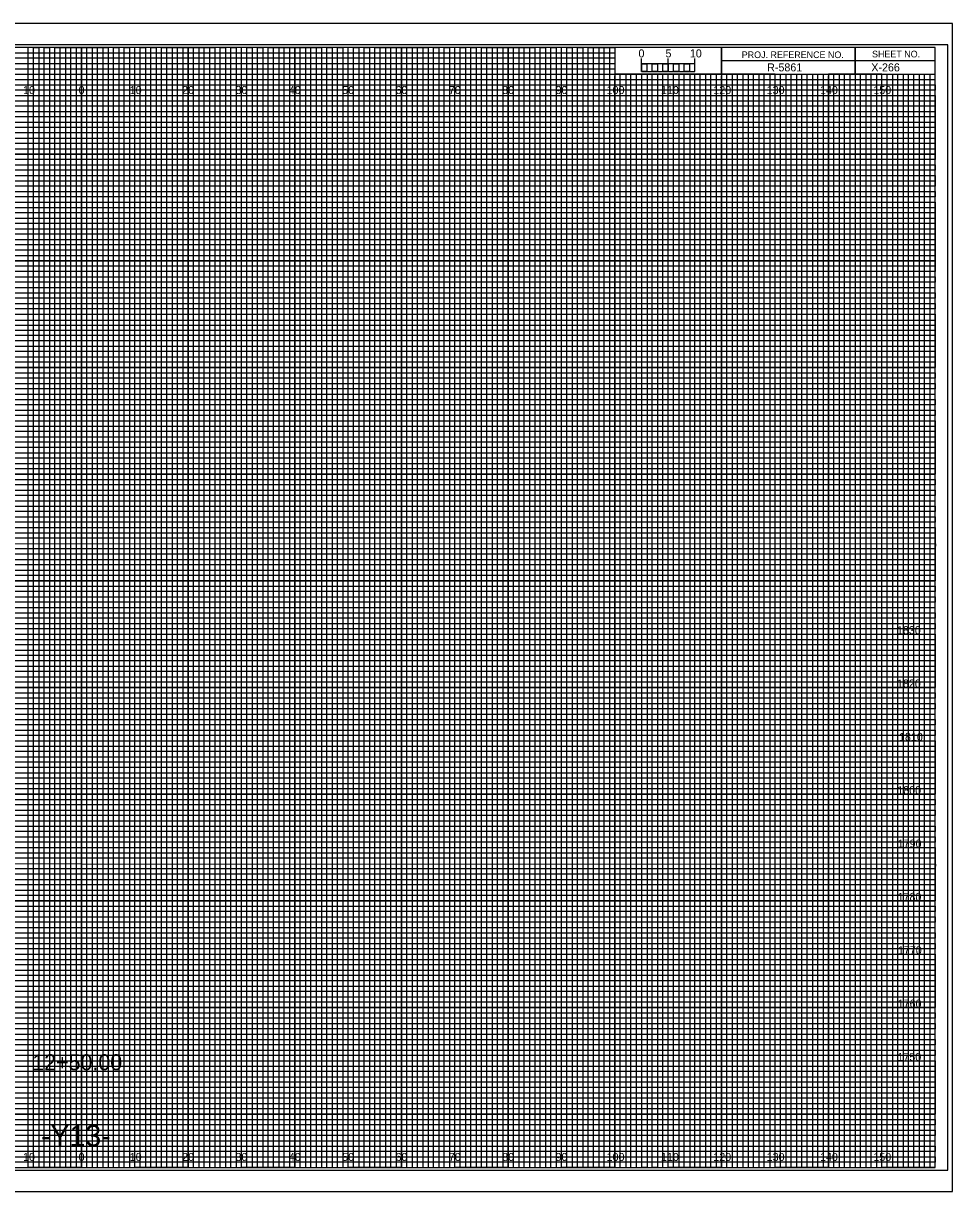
# Model space of a CAD drawing. Extents: x -13 to 323, y -5 to 654.
# Drawn here: x 149.1 to 323.3, y 435.5 to 654.5 of the extents above; entities that cross this region are included whole.
import ezdxf

# ---------------------------------------------------------------- set-up
doc = ezdxf.new("R2010")
doc.units = 0
for name, color, linetype in [('Prop Horizontal Alignment', 7, 'Continuous'), ('Prop XS Alignment Label', 7, 'Continuous'), ('Prop XS Bar Scale Labels', 7, 'Continuous'), ('Prop XS DDE', 7, 'Continuous'), ('Prop XS Earthwork Shape', 7, 'Continuous'), ('Prop XS Project Number', 7, 'Continuous'), ('Prop XS Sheet Number', 7, 'Continuous'), ('Raster_Level_0', 7, 'Continuous'), ('Scratch_Level_3', 7, 'Continuous'), ('Sheet Cross Section CELL', 7, 'Continuous'), ('Sheet Cross Section Grid Minor 1 CELL', 7, 'Continuous'), ('Sheet Cross Section Grid Minor 2 CELL', 7, 'Continuous'), ('Sheet Cross Section Scale CELL', 7, 'Continuous'), ('Sheet Cutting Line CELL', 7, 'Continuous'), ('Sheet DOT Grid CELL', 7, 'Continuous'), ('Sheet Plot Border Inside CELL', 7, 'Continuous'), ('Sheet Plot Border Outside CELL', 7, 'Continuous')]:
    doc.layers.add(name, color=color, linetype=linetype)

msp = doc.modelspace()

# ---------------------------------------------------------------- linework, layer by layer
at = {"layer": 'Prop XS DDE'}
for points in [[(145, 440), (155, 440), (155, 650), (165, 650), (165, 440), (175, 440), (175, 650), (185, 650), (185, 440), (195, 440), (195, 650), (205, 650), (205, 440), (215, 440), (215, 650), (225, 650), (225, 440), (235, 440), (235, 650), (245, 650), (245, 440), (255, 440), (255, 650), (259.93, 650), (260, 650), (260, 645), (264.99, 645), (264.99, 440), (275, 440), (275, 645), (285, 645), (285, 440), (295, 440), (295, 645), (305, 645), (305, 440), (315, 440), (315, 645)], [(0, 645), (275, 645)], [(0, 625), (320, 625), (320, 635), (0, 635)], [(0, 605), (320, 605), (320, 615), (0, 615)], [(0, 585), (320, 585), (320, 595), (0, 595)], [(0, 565), (320, 565), (320, 575), (0, 575)], [(0, 545), (320, 545), (320, 555), (0, 555)], [(0, 525), (320, 525), (320, 535), (0, 535)], [(0, 505), (320, 505), (320, 515), (0, 515)], [(0, 485), (320, 485), (320, 495), (0, 495)], [(0, 465), (320, 465), (320, 475), (0, 475)], [(0, 445), (320, 445), (320, 455), (0, 455)]]:
    msp.add_lwpolyline(points, dxfattribs=at)
at = {"layer": 'Prop XS Earthwork Shape'}
for p, q in [((150, 650), (140, 650)), ((150, 440), (150, 650)), ((170, 650), (160, 650)), ((160, 650), (160, 440)), ((170, 440), (170, 650)), ((190, 650), (180, 650)), ((180, 650), (180, 440)), ((190, 440), (190, 650)), ((210, 650), (200, 650)), ((200, 650), (200, 440)), ((210, 440), (210, 650)), ((230, 650), (220, 650)), ((220, 650), (220, 440)), ((230, 440), (230, 650)), ((250, 650), (240, 650)), ((240, 650), (240, 440)), ((250, 440), (250, 650)), ((260, 650), (260, 440)), ((270, 440), (270, 645)), ((290, 645), (280, 645)), ((280, 645), (280, 440)), ((290, 440), (290, 645)), ((310, 645), (300, 645)), ((300, 645), (300, 440)), ((310, 440), (310, 645)), ((160, 440), (150, 440)), ((180, 440), (170, 440)), ((200, 440), (190, 440)), ((220, 440), (210, 440)), ((240, 440), (230, 440)), ((260, 440), (250, 440)), ((280, 440), (270, 440)), ((300, 440), (290, 440)), ((320, 440), (310, 440)), ((320, 440), (320, 440))]:
    msp.add_line(p, q, dxfattribs=at)
for points in [[(0, 640), (320, 640), (320, 630), (0, 630)], [(0, 620), (320, 620), (320, 610), (0, 610)], [(0, 600), (320, 600), (320, 590), (0, 590)], [(0, 580), (320, 580), (320, 570), (0, 570)], [(0, 560), (320, 560), (320, 550), (0, 550)], [(0, 540), (320, 540), (320, 530), (0, 530)], [(0, 520), (320, 520), (320, 510), (0, 510)], [(0, 500), (320, 500), (320, 490), (0, 490)], [(0, 480), (320, 480), (320, 470), (0, 470)], [(0, 460), (320, 460), (320, 450), (0, 450)]]:
    msp.add_lwpolyline(points, dxfattribs=at)
at = {"layer": 'Sheet Cross Section CELL'}
for p, q in [((305, 650), (305, 645)), ((305, 645), (305, 650)), ((280, 647.5), (280, 645)), ((320, 647.49), (280, 647.49)), ((280, 645), (320, 645))]:
    msp.add_line(p, q, dxfattribs=at)
for points in [[(320, 650), (0, 650), (0, 440), (320, 440)], [(280, 650), (260, 650), (260, 645.03), (280, 645.03)], [(320, 650), (280, 650), (280, 645), (320, 645)]]:
    msp.add_lwpolyline(points, close=True, dxfattribs=at)
at = {"layer": 'Sheet Cross Section Grid Minor 1 CELL'}
for p, q in [((0, 649), (260, 649)), ((260, 649), (260, 647.98)), ((260, 647.98), (0, 647.98)), ((0, 647), (260, 647)), ((260, 647), (260, 645.89)), ((260, 645.89), (0, 645.89)), ((0, 644), (320, 644))]:
    msp.add_line(p, q, dxfattribs=at)
for points in [[(0, 643), (270, 643), (320, 643), (320, 642), (0, 642)], [(0, 641), (320, 641), (320, 639), (0, 639)], [(0, 638), (320, 638), (320, 637), (0, 636.98)], [(0, 636), (320, 636), (320, 634), (0, 634)], [(0, 633), (320, 633), (320, 632), (0, 632)], [(0, 631), (320, 631), (320, 629), (0, 629)], [(0, 628), (320, 628), (320, 627), (0, 627)], [(0, 626), (320, 626), (320, 624), (0, 624)], [(0, 623), (320, 623), (320, 622), (0, 622)], [(0, 621), (320, 621), (320, 619), (0, 619)], [(0, 618), (320, 618), (320, 617), (0, 617)], [(0, 616), (320, 616), (320, 613.95), (320, 613), (320, 612), (0, 612)], [(0, 614), (320, 614), (320, 613), (0, 613)], [(0, 611), (320, 611), (320, 609), (0, 609.03)], [(0, 609.03), (320, 609), (320, 608), (0, 608)], [(0, 607), (320, 607), (320, 606), (0, 606)], [(0, 604), (320, 604), (320, 603), (0, 603)], [(0, 602), (320, 602), (320, 601), (0, 601)], [(-0.07, 598.89), (320, 598.89), (320, 597.88), (-0.07, 597.88)], [(0, 597), (320, 597), (320, 596), (0, 596)], [(0, 594), (320, 594), (320, 593), (0, 593)], [(0, 592), (320, 592), (320, 591), (0, 591)], [(0, 589), (320, 589), (320, 588), (0, 588)], [(0, 587), (320, 587), (320, 586), (0, 586)], [(0, 584), (320, 584), (320, 583), (0, 583)], [(0, 582), (320, 582), (320, 581), (0, 581)], [(0, 579), (320, 579), (319.99, 577.98), (0, 578)], [(0, 577), (320, 577), (320, 576), (0, 576)], [(0, 574), (320, 574), (320, 573), (0, 573)], [(0, 572), (320, 572), (320, 571), (0, 571)], [(0, 569), (320, 569), (320, 568), (0, 568)], [(0, 567), (320, 567), (320, 566), (0, 566)], [(0, 564), (320, 564), (320, 563), (0, 563)], [(0, 562), (320, 562), (320, 561), (0, 561)], [(0, 559), (320, 559), (320, 558), (0, 558)], [(0, 556.99), (320.07, 556.91), (320, 556), (0, 556)], [(0, 554), (320, 554), (320, 553), (0, 553)], [(0, 552), (320, 552), (320, 551), (0, 551)], [(0, 549), (320, 549), (320, 548), (0, 548)], [(0, 547), (320, 547), (320, 546), (0, 546)], [(0, 544), (320, 544), (320, 543), (0, 543)], [(0, 542), (320, 542), (320, 541), (0, 541)], [(0, 539), (320, 539), (320, 538), (0, 538)], [(0, 537), (320, 537), (320, 536), (0, 536)], [(0, 534), (320, 534), (320, 533), (0, 533)], [(0, 532), (320, 532), (320, 531), (0, 531)], [(0, 529), (320, 529), (320, 528), (0, 528)], [(0, 527), (320, 527), (320, 526), (0, 526)], [(0, 524), (320, 524), (320, 523), (0, 523)], [(0, 522), (320, 522), (320, 521), (0, 521)], [(0, 519), (320, 519), (319.99, 517.98), (0, 518)], [(0, 517), (320, 517), (320, 516), (0, 516)], [(0, 514), (320, 514), (320, 513), (0, 513)], [(0, 512), (320, 512), (320, 511), (0, 511)], [(0, 509), (320, 509), (320, 508), (0, 508)], [(0, 507), (320, 507), (320, 506), (0, 506)], [(0, 504), (320, 504), (320, 503), (0, 503)], [(0, 502), (320, 502), (320, 501), (0, 501)], [(0, 499), (320, 499), (320, 498), (0, 498)], [(0, 496.99), (320.07, 496.91), (320, 496), (0, 496)], [(0, 494), (320, 494), (320, 493), (0, 493)], [(0, 492), (320, 492), (320, 491), (0, 491)], [(0, 489), (320, 489), (320, 488), (0, 488)], [(0, 487), (320, 487), (320, 486), (0, 486)], [(0, 484), (320, 484), (320, 483), (0, 483)], [(0, 482), (320, 482), (320, 481), (0, 481)], [(0, 479), (320, 479), (320, 478), (0, 478)], [(0, 477), (320, 477), (320, 476), (0, 476)], [(0, 474), (320, 474), (320, 473), (0, 473)], [(0, 472), (320, 472), (320, 471), (0, 471)], [(0, 469), (320, 469), (320, 468), (0, 468)], [(0, 467), (320, 467), (320, 466), (0, 466)], [(0, 464), (320, 464), (320, 463), (0, 463)], [(0, 462), (320, 462), (320, 461), (0, 461)], [(0, 459), (320, 459), (320, 458), (0, 458)], [(0, 457), (320, 457), (320, 456), (0, 456)], [(0, 454), (320, 454), (320, 453), (0, 453)], [(0, 452), (320, 452), (320, 451), (0, 451)], [(0, 449), (320, 449), (320, 448), (0, 448)], [(0, 447), (320, 447), (320, 446), (0, 446)], [(0, 444), (320, 444), (320, 443), (0, 443)], [(0, 442), (320, 442), (320, 441), (0, 441)]]:
    msp.add_lwpolyline(points, dxfattribs=at)
at = {"layer": 'Sheet Cross Section Grid Minor 2 CELL'}
for p, q in [((267, 645), (266.01, 645)), ((266.01, 645), (266.01, 440)), ((267, 440), (267, 645)), ((269, 645), (268, 645)), ((268, 645), (268, 440)), ((269, 440), (269, 645)), ((266.01, 440), (265, 440)), ((268, 440), (267, 440))]:
    msp.add_line(p, q, dxfattribs=at)
for points in [[(150, 440), (151, 440), (151, 650), (152, 650), (152, 440)], [(152, 440), (153, 440), (153, 650), (154, 650), (154, 440)], [(155, 440), (156, 440), (156, 650), (157, 650), (157, 440)], [(157, 440), (158, 440), (158, 650), (159, 650), (159, 440)], [(160, 440), (161, 440), (161, 650), (162, 650), (162, 440)], [(162, 440), (163, 440), (163, 650), (164, 650), (164, 440)], [(165, 440), (166, 440), (166, 650), (167, 650), (167, 440)], [(167, 440), (168, 440), (168, 650), (169, 650), (169, 440)], [(170, 440), (171, 440), (171, 650), (172, 650), (172, 440)], [(172, 440), (173, 440), (173, 650), (174, 650), (174, 440)], [(175, 440), (176, 440), (176, 650), (177, 650), (177, 440)], [(177, 440), (178, 440), (178, 650), (179, 650), (179, 440)], [(180, 440), (181, 440), (181, 650), (182, 650), (182, 440)], [(182, 440), (183, 440), (183, 650), (184, 650), (184, 440)], [(185, 440), (186, 440), (186, 650), (187, 650), (187, 440)], [(187, 440), (188, 440), (188, 650), (189, 650), (189, 440)], [(190, 440), (191, 440), (191, 650), (192, 650), (192, 440)], [(192, 440), (193, 440), (193, 650), (194, 650), (194, 440)], [(195, 440), (196, 440), (196, 650), (197, 650), (197, 440)], [(197, 440), (198, 440), (198, 650), (199, 650), (199, 440)], [(200, 440), (201, 440), (201, 650), (202, 650), (202, 440)], [(202, 440), (203, 440), (203, 650), (204, 650), (204, 440)], [(205, 440), (206, 440), (206, 650), (207, 650), (207, 440)], [(207, 440), (208, 440), (208, 650), (209, 650), (209, 440)], [(210, 440), (211, 440), (211, 650), (212, 650), (212, 440)], [(212, 440), (213, 440), (213, 650), (214, 650), (214, 440)], [(215, 440), (216, 440), (216, 650), (217, 650), (217, 440)], [(217, 440), (218, 440), (218, 650), (219, 650), (219, 440)], [(220, 440), (221, 440), (221, 650), (222, 650), (222, 440)], [(222, 440), (223, 440), (223, 650), (224, 650), (224, 440)], [(225, 440), (226, 440), (226, 650), (227, 650), (227, 440)], [(227, 440), (228, 440), (228, 650), (229, 650), (229, 440)], [(230, 440), (231, 440), (231, 650), (232, 650), (232, 440)], [(232, 440), (233, 440), (233, 650), (234, 650), (234, 440)], [(235, 440), (236, 440), (236, 650), (237, 650), (237, 440)], [(237, 440), (238, 440), (238, 650), (239, 650), (239, 440)], [(240, 440), (241, 440), (241, 650), (242, 650), (242, 440)], [(242, 440), (243, 440), (243, 650), (244, 650), (244, 440)], [(245, 440), (246, 440), (246, 650), (247, 650), (247, 440)], [(247, 440), (248, 440), (248, 650), (249, 650), (249, 440)], [(250, 440), (251, 440), (251, 650), (252, 650), (252, 440)], [(252, 440), (253, 440), (253, 650), (254, 650), (254, 440)], [(255, 440), (256, 440), (256, 650), (257, 650), (257, 440)], [(257, 440), (258, 440), (258, 650), (259, 650), (259, 440)], [(260, 440), (261, 440), (261, 645), (262.02, 645), (262.02, 440)], [(262, 440), (263, 440), (263, 645), (263.99, 645), (263.99, 440)], [(270, 440), (270.98, 440), (270.98, 645), (272, 645), (272, 440)], [(272, 440), (273, 440), (273, 645), (274.05, 645), (274.05, 440)], [(275, 440), (276, 440), (276, 645), (277, 645), (277, 440)], [(277, 440), (278, 440), (278, 645), (279, 645), (279, 440)], [(280, 440), (281, 440), (281, 645), (282, 645), (282, 440)], [(282, 440), (283, 440), (283, 645), (284, 645), (284, 440)], [(285, 440), (286, 440), (286, 645), (287, 645), (287, 440)], [(287, 440), (288, 440), (288, 645), (289, 645), (289, 440)], [(290, 440), (291, 440), (291, 645), (292, 645), (292, 440)], [(292, 440), (293, 440), (293, 645), (294, 645), (294, 440)], [(295, 440), (296, 440), (296, 645), (297, 645), (297, 440)], [(297, 440), (298, 440), (298, 645), (299, 645), (299, 440)], [(300, 440), (301, 440), (301, 645), (302, 645), (302, 440)], [(302, 440), (303, 440), (303, 645), (304, 645), (304, 440)], [(305, 440), (306, 440), (306, 645), (307, 645), (307, 440)], [(307, 440), (308, 440), (308, 645), (309, 645), (309, 440)], [(310, 440), (311, 440), (311, 645), (312, 645), (312, 440)], [(312, 440), (313, 440), (313, 645), (314, 645), (314, 440)], [(315, 440), (316, 440), (316, 645), (317, 645), (317, 440)], [(317, 440), (318, 440), (318, 645), (319, 645), (319, 440)]]:
    msp.add_lwpolyline(points, dxfattribs=at)
at = {"layer": 'Sheet Cross Section Scale CELL'}
for p, q in [((265, 645.49), (265, 647.9)), ((265, 646.9), (265, 647.9)), ((270, 645.49), (270, 647.9)), ((275, 645.49), (275, 647.9)), ((275, 646.9), (275, 647.9))]:
    msp.add_line(p, q, dxfattribs=at)
for points in [[(275, 646.9), (265, 646.9), (265, 645.49), (275, 645.49)], [(265, 646.9), (266, 646.9), (266, 645.49), (265, 645.49)], [(267, 646.9), (268, 646.9), (268, 645.49), (267, 645.49)], [(269, 646.9), (270, 646.9), (270, 645.49), (269, 645.49)], [(271, 646.9), (272, 646.9), (272, 645.49), (271, 645.49)], [(273, 646.9), (274, 646.9), (274, 645.49), (273, 645.49)]]:
    msp.add_lwpolyline(points, close=True, dxfattribs=at)
at = {"layer": 'Sheet Cutting Line CELL'}
for p, q in [((323.3, 654.5), (-13.4, 654.5)), ((-13.4, 435.5), (323.3, 435.5))]:
    msp.add_line(p, q, dxfattribs=at)
at = {"layer": 'Sheet DOT Grid CELL'}
for p, q in [((150, 440), (150, 650)), ((160, 440), (160, 650)), ((170, 440), (170, 650)), ((180, 440), (180, 650)), ((190, 440), (190, 650)), ((200, 440), (200, 650)), ((210, 440), (210, 650)), ((220, 440), (220, 650)), ((230, 440), (230, 650)), ((240, 440), (240, 650)), ((250, 440), (250, 650)), ((260, 440), (260, 644.69)), ((270, 440), (270, 644.69)), ((280, 440), (280, 644.69)), ((290, 440), (290, 644.69)), ((300, 440), (300, 644.69)), ((310, 440), (310, 644.69)), ((0, 640), (320, 640)), ((0, 630), (320, 630)), ((0, 620), (320, 620)), ((0, 610), (320, 610)), ((0, 600), (320, 600)), ((0, 590), (320, 590)), ((0, 580), (320, 580)), ((0, 570), (320, 570)), ((0, 560), (320, 560)), ((0, 550), (320, 550)), ((0, 540), (320, 540)), ((0, 530), (320, 530)), ((0, 520), (320, 520)), ((0, 510), (320, 510)), ((0, 500), (320, 500)), ((0, 490), (320, 490)), ((0, 480), (320, 480)), ((0, 470), (320, 470)), ((0, 460), (320, 460)), ((0, 450), (320, 450))]:
    msp.add_line(p, q, dxfattribs=at)
at = {"layer": 'Sheet Plot Border Inside CELL'}
msp.add_lwpolyline([(-10.8, 439.5), (322.4, 439.5), (322.4, 650.5), (-10.8, 650.5)], close=True, dxfattribs=at)
at = {"layer": 'Sheet Plot Border Outside CELL'}
msp.add_lwpolyline([(-13.4, 435.5), (323.3, 435.5), (323.3, 654.5), (-13.4, 654.5)], close=True, dxfattribs=at)

# ---------------------------------------------------------------- texts
at = {"layer": 'Prop Horizontal Alignment'}
msp.add_text('12+50.00', height=3, dxfattribs=at).set_placement((150.77, 458.25))
at = {"layer": 'Prop XS Alignment Label'}
msp.add_text('-Y13-', height=4, dxfattribs=at).set_placement((152.39, 444))
at = {"layer": 'Prop XS Bar Scale Labels'}
for s, p in [('5', (269.47, 648.12)), ('10', (274.04, 648.12))]:
    msp.add_text(s, height=1.5, dxfattribs=at).set_placement(p)
at = {"layer": 'Prop XS Project Number'}
msp.add_text('R-5861', height=1.5, dxfattribs=at).set_placement((288.53, 645.5))
at = {"layer": 'Prop XS Sheet Number'}
msp.add_text('X-266', height=1.5, dxfattribs=at).set_placement((308.05, 645.5))
at = {"layer": 'Raster_Level_0'}
for s, p in [('10', (149.04, 641.25)), ('0', (159.45, 641.25)), ('0', (159.45, 641.25)), ('10', (169.04, 641.25)), ('20', (178.86, 641.25)), ('30', (188.86, 641.25)), ('40', (198.86, 641.25)), ('50', (208.86, 641.25)), ('60', (218.86, 641.25)), ('70', (228.86, 641.25)), ('80', (238.86, 641.25)), ('90', (248.86, 641.25)), ('100', (258.44, 641.25)), ('110', (268.62, 641.25)), ('120', (278.44, 641.25)), ('130', (288.44, 641.25)), ('140', (298.44, 641.25)), ('150', (308.44, 641.25)), ('10', (149.04, 441.25)), ('0', (159.45, 441.25)), ('0', (159.45, 441.25)), ('10', (169.04, 441.25)), ('20', (178.86, 441.25)), ('30', (188.86, 441.25)), ('40', (198.86, 441.25)), ('50', (208.86, 441.25)), ('60', (218.86, 441.25)), ('70', (228.86, 441.25)), ('80', (238.86, 441.25)), ('90', (248.86, 441.25)), ('100', (258.44, 441.25)), ('110', (268.62, 441.25)), ('120', (278.44, 441.25)), ('130', (288.44, 441.25)), ('140', (298.44, 441.25)), ('150', (308.44, 441.25))]:
    msp.add_text(s, height=1.5, dxfattribs=at).set_placement(p)
at = {"layer": 'Scratch_Level_3'}
for s, p in [('1830', (312.86, 540)), ('1820', (312.87, 530)), ('1810', (313.25, 520)), ('1800', (312.92, 510)), ('1790', (313, 500)), ('1780', (312.98, 490)), ('1770', (313.04, 480)), ('1760', (313, 470)), ('1750', (312.96, 460))]:
    msp.add_text(s, height=1.5, dxfattribs=at).set_placement(p)
at = {"layer": 'Sheet Cross Section CELL'}
for s, p in [('PROJ. REFERENCE NO.', (283.77, 647.99)), ('SHEET NO.', (308.19, 648.12))]:
    msp.add_text(s, height=1.25, dxfattribs=at).set_placement(p)
at = {"layer": 'Sheet Cross Section Scale CELL'}
msp.add_text('0', height=1.5, dxfattribs=at).set_placement((264.41, 648.12))

doc.saveas('drawing.dxf')
